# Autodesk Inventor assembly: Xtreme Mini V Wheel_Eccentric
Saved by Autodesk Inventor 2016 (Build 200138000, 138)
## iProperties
Created: 2015-11
Part Number: Xtreme Mini V Wheel_Eccentric
Document SubType Name: Assembly
Designer: John
Author: John
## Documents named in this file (6)
- D:\3D Printer Designs\John Ledden Designs\DLP Printer\V0-4\Xtreme Mini V Wheel_Eccentric.iam
- D:\3D Printer Designs\John Ledden Designs\DLP Printer\V0-4\Xtreme Mini V Wheel.ipt
- D:\3D Printer Designs\John Ledden Designs\DLP Printer\V0-4\Ball Bearing 5 x 10 x 4.2.ipt
- D:\3D Printer Designs\John Ledden Designs\DLP Printer\V0-4\Precision Shim 8 x 5 x 1.ipt
- D:\3D Printer Designs\John Ledden Designs\DLP Printer\V0-4\Nylon Insert Lock Nut M5.ipt
- D:\3D Printer Designs\John Ledden Designs\DLP Printer\V0-4\Mini Eccentric Spacer 6mm.ipt
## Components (7 placed, 7 different names)
1. Xtreme Mini V Wheel_1088
2. Ball Bearing 5 x 10 x 4.2_1089
3. Ball Bearing 5 x 10 x 4.2_1090
4. Precision Shim 8 x 5 x 1_1091
5. Precision Shim 8 x 5 x 1_1092
6. Nylon Insert Lock Nut M5_1093
7. Mini Eccentric Spacer 6mm_1094
